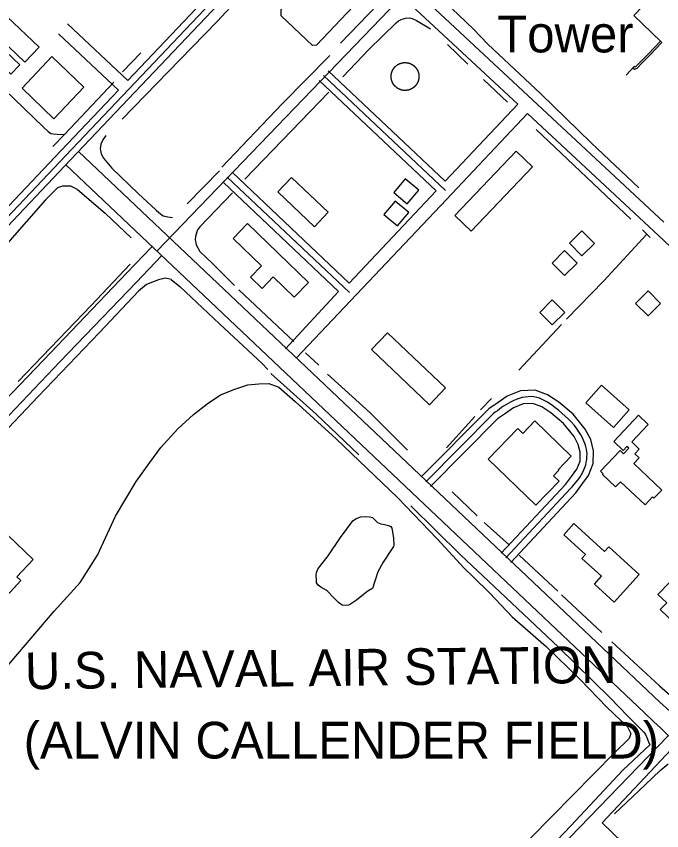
# Model space of a CAD drawing. Extents: x 3683613 to 3738215, y 469626 to 495384.
# Drawn here: x 3696220 to 3697680, y 483982 to 485823 of the extents above; entities that cross this region are included whole.
import ezdxf

# ---------------------------------------------------------------- set-up
doc = ezdxf.new("R2010")
doc.units = 0
for name, color, linetype in [('V-BLDG-IDEN', 7, 'Continuous'), ('V-BLDG-OTLN', 7, 'Continuous'), ('V-DOMW-IDEN', 7, 'Continuous'), ('V-DOMW-TANK', 7, 'Continuous'), ('V-ROAD-CNTR', 7, 'Continuous'), ('V-SITE-OTLN', 7, 'Continuous'), ('V-TOPO-SHOR', 7, 'Continuous'), ('V-UTIL-LINE', 7, 'Continuous')]:
    doc.layers.add(name, color=color, linetype=linetype)

msp = doc.modelspace()

# ---------------------------------------------------------------- linework, layer by layer
at = {"layer": 'V-BLDG-OTLN'}
for points in [[(3696925.1, 485938), (3696996.9, 485871.2), (3696996, 485859.8), (3696899.4, 485757.8), (3696890.2, 485757.5), (3696819.6, 485824.5), (3696819.4, 485838.4), (3696915.4, 485938.3)], [(3696118.3, 485817.2), (3696228.1, 485713.7), (3696207.9, 485692.3), (3696098.7, 485795.2)], [(3696199.1, 485822.8), (3696271.8, 485753.6), (3696239.5, 485719.7), (3696166.1, 485789.6)], [(3696300.7, 485732.5), (3696373.4, 485662.7), (3696305.2, 485591.7), (3696233.5, 485660.5)], [(3697212, 485372.9), (3697350.9, 485517.9), (3697387.9, 485482.5), (3697249.1, 485337.4)], [(3696842.6, 485458.9), (3696925.9, 485380), (3696895.1, 485347.5), (3696811.8, 485426.4)], [(3697100, 485455.6), (3697074.3, 485425), (3697104.9, 485399.3), (3697130.7, 485429.9)], [(3697077.7, 485405.4), (3697052, 485374.8), (3697082.6, 485349.1), (3697108.4, 485379.7)], [(3696743.1, 485354.6), (3696881.3, 485221.3), (3696849.3, 485188.1), (3696801.8, 485233.9), (3696776.9, 485208.1), (3696750.3, 485233.7), (3696774.9, 485259.2), (3696710.7, 485321)], [(3697499.6, 485281.6), (3697528, 485309.8), (3697499.8, 485338.2), (3697471.4, 485309.9)], [(3697460.6, 485237), (3697489, 485265.2), (3697460.7, 485293.5), (3697432.4, 485265.3)], [(3697621.3, 485173.9), (3697649.7, 485145.8), (3697677.9, 485174.1), (3697649.5, 485202.3)], [(3697432.7, 485125.5), (3697461.1, 485153.7), (3697432.9, 485182), (3697404.5, 485153.8)], [(3697155.1, 484945), (3697023.9, 485069.7), (3697060, 485107.7), (3697191.2, 484983)], [(3697571, 484893.8), (3697508.5, 484949.6), (3697544.1, 484989.5), (3697606.6, 484933.7)], [(3697287.8, 484821.6), (3697354.8, 484891.1), (3697366.2, 484880.2), (3697393.1, 484908.2), (3697475.8, 484828.5), (3697446.3, 484797.8), (3697447.4, 484796.8), (3697435.3, 484784.2), (3697448, 484771.9), (3697395.7, 484717.6)], [(3697680.3, 484751.9), (3697662.8, 484733.4), (3697659.6, 484736.4), (3697642.6, 484718.5), (3697587.2, 484770.9), (3697576, 484759), (3697546.4, 484787.1), (3697547.9, 484788.6), (3697541.6, 484794.6), (3697586.2, 484841.6), (3697593.9, 484834.3), (3697605.6, 484846.6), (3697601.4, 484850.5), (3697593.2, 484841.8), (3697571.8, 484862.1), (3697627.6, 484921), (3697649.8, 484899.9), (3697612.6, 484860.7), (3697629.4, 484844.8), (3697619.4, 484834.3), (3697629.3, 484824.9), (3697617, 484812)], [(3696169.4, 484644), (3696154.5, 484628), (3696168.9, 484614.3), (3696201.8, 484649), (3696258.6, 484595.2), (3696221.4, 484556.1), (3696230.8, 484547.2), (3696182.1, 484495.8), (3696046.1, 484624.9), (3696052.2, 484631.3), (3696046.2, 484636.9), (3696108.1, 484702.2)], [(3697629.5, 484560.9), (3697572.9, 484498.7), (3697528, 484539.5), (3697544, 484557.1), (3697499.9, 484597.2), (3697507.9, 484606), (3697458.6, 484650.9), (3697481.8, 484676.4), (3697551.2, 484613.3), (3697560.6, 484623.5)], [(3697895.6, 484510.5), (3697777.2, 484387.8), (3697745.6, 484418.2), (3697741.5, 484414), (3697709.5, 484444.9), (3697712.3, 484447.8), (3697677.1, 484481.7), (3697691.7, 484496.8), (3697671.8, 484516), (3697750.6, 484597.6), (3697778.3, 484571), (3697793, 484586.3), (3697800.6, 484579), (3697803.2, 484581.7), (3697817.2, 484568.3), (3697814.1, 484565), (3697833.4, 484546.4), (3697844.4, 484557.9), (3697852.3, 484550.3), (3697855, 484553.2), (3697863.1, 484545.4), (3697861.3, 484543.5)]]:
    msp.add_lwpolyline(points, close=True, dxfattribs=at)
at = {"layer": 'V-DOMW-TANK'}
for points in [[(3697071.1, 485674), (3697070.9, 485674.5), (3697070.7, 485675), (3697070.5, 485675.5), (3697070.3, 485676), (3697070.1, 485676.5), (3697069.9, 485677.1), (3697069.7, 485677.6), (3697069.6, 485678.1), (3697069.4, 485678.6), (3697069.3, 485679.2), (3697069.1, 485679.7), (3697069, 485680.2), (3697068.9, 485680.8), (3697068.8, 485681.3), (3697068.7, 485681.9), (3697068.6, 485682.4), (3697068.5, 485682.9), (3697068.5, 485683.5), (3697068.4, 485684), (3697068.4, 485684.6), (3697068.3, 485685.1), (3697068.3, 485685.7), (3697068.3, 485686.2), (3697068.3, 485686.8), (3697068.3, 485687.3), (3697068.3, 485687.9), (3697068.3, 485688.4), (3697068.3, 485689), (3697068.4, 485689.5), (3697068.4, 485690.1), (3697068.5, 485690.6), (3697068.5, 485691.2), (3697068.6, 485691.7), (3697068.7, 485692.3), (3697068.8, 485692.8), (3697068.9, 485693.3), (3697069, 485693.9), (3697069.1, 485694.4), (3697069.3, 485694.9), (3697069.4, 485695.5), (3697069.6, 485696), (3697069.7, 485696.5), (3697069.9, 485697), (3697070.1, 485697.6), (3697070.3, 485698.1), (3697070.5, 485698.6), (3697070.7, 485699.1), (3697070.9, 485699.6), (3697071.1, 485700.1), (3697071.3, 485700.6), (3697071.6, 485701.1), (3697071.8, 485701.6), (3697072.1, 485702.1), (3697072.4, 485702.6), (3697072.6, 485703), (3697072.9, 485703.5), (3697073.2, 485704), (3697073.5, 485704.4), (3697073.8, 485704.9), (3697074.1, 485705.3), (3697074.5, 485705.8), (3697074.8, 485706.2), (3697075.1, 485706.7), (3697075.5, 485707.1), (3697075.8, 485707.5), (3697076.2, 485707.9), (3697076.5, 485708.3), (3697076.9, 485708.7), (3697077.3, 485709.1), (3697077.7, 485709.5), (3697078.1, 485709.9), (3697078.5, 485710.3), (3697078.9, 485710.6), (3697079.3, 485711), (3697079.7, 485711.4), (3697080.2, 485711.7), (3697080.6, 485712), (3697081, 485712.4), (3697081.5, 485712.7), (3697081.9, 485713), (3697082.4, 485713.3), (3697082.9, 485713.6), (3697083.3, 485713.9), (3697083.8, 485714.2), (3697084.3, 485714.5), (3697084.7, 485714.7), (3697085.2, 485715), (3697085.7, 485715.2), (3697086.2, 485715.5), (3697086.7, 485715.7), (3697087.2, 485715.9), (3697087.7, 485716.2), (3697088.2, 485716.4), (3697088.7, 485716.6), (3697089.3, 485716.7), (3697089.8, 485716.9), (3697090.3, 485717.1), (3697090.8, 485717.3), (3697091.4, 485717.4), (3697091.9, 485717.5)], [(3697091.9, 485717.5), (3697092.4, 485717.7), (3697093, 485717.8), (3697093.5, 485717.9), (3697094, 485718), (3697094.6, 485718.1), (3697095.1, 485718.2), (3697095.7, 485718.3), (3697096.2, 485718.3), (3697096.8, 485718.4), (3697097.3, 485718.5), (3697097.9, 485718.5), (3697098.4, 485718.5), (3697099, 485718.5), (3697099.5, 485718.5), (3697100.1, 485718.5), (3697100.6, 485718.5), (3697101.2, 485718.5), (3697101.7, 485718.5), (3697102.2, 485718.5), (3697102.8, 485718.4), (3697103.3, 485718.3), (3697103.9, 485718.3), (3697104.4, 485718.2), (3697105, 485718.1), (3697105.5, 485718), (3697106.1, 485717.9), (3697106.6, 485717.8), (3697107.1, 485717.7), (3697107.7, 485717.5), (3697108.2, 485717.4), (3697108.7, 485717.2), (3697109.2, 485717.1), (3697109.8, 485716.9), (3697110.3, 485716.7), (3697110.8, 485716.6), (3697111.3, 485716.4), (3697111.8, 485716.1), (3697112.3, 485715.9), (3697112.8, 485715.7), (3697113.3, 485715.5), (3697113.8, 485715.2), (3697114.3, 485715), (3697114.8, 485714.7), (3697115.3, 485714.5), (3697115.8, 485714.2), (3697116.2, 485713.9), (3697116.7, 485713.6), (3697117.2, 485713.3), (3697117.6, 485713), (3697118.1, 485712.7), (3697118.5, 485712.4), (3697119, 485712), (3697119.4, 485711.7), (3697119.8, 485711.3), (3697120.2, 485711), (3697120.6, 485710.6), (3697121.1, 485710.3), (3697121.5, 485709.9), (3697121.9, 485709.5), (3697122.2, 485709.1), (3697122.6, 485708.7), (3697123, 485708.3), (3697123.4, 485707.9), (3697123.7, 485707.5), (3697124.1, 485707.1), (3697124.4, 485706.7), (3697124.8, 485706.2), (3697125.1, 485705.8), (3697125.4, 485705.3), (3697125.7, 485704.9), (3697126, 485704.4), (3697126.3, 485704), (3697126.6, 485703.5), (3697126.9, 485703), (3697127.2, 485702.6), (3697127.5, 485702.1), (3697127.7, 485701.6), (3697128, 485701.1), (3697128.2, 485700.6), (3697128.4, 485700.1), (3697128.7, 485699.6), (3697128.9, 485699.1), (3697129.1, 485698.6), (3697129.3, 485698.1), (3697129.5, 485697.6), (3697129.6, 485697), (3697129.8, 485696.5), (3697130, 485696), (3697130.1, 485695.5), (3697130.3, 485694.9), (3697130.4, 485694.4), (3697130.5, 485693.9), (3697130.6, 485693.3), (3697130.7, 485692.8), (3697130.8, 485692.2), (3697130.9, 485691.7), (3697131, 485691.2), (3697131.1, 485690.6), (3697131.1, 485690.1), (3697131.2, 485689.5)], [(3697131.2, 485689.5), (3697131.2, 485689), (3697131.2, 485688.4), (3697131.3, 485687.9), (3697131.3, 485687.3), (3697131.3, 485686.8), (3697131.3, 485686.2), (3697131.2, 485685.7), (3697131.2, 485685.1), (3697131.2, 485684.6), (3697131.1, 485684), (3697131.1, 485683.5), (3697131, 485682.9), (3697130.9, 485682.4), (3697130.8, 485681.8), (3697130.7, 485681.3), (3697130.6, 485680.8), (3697130.5, 485680.2), (3697130.4, 485679.7), (3697130.3, 485679.2), (3697130.1, 485678.6), (3697130, 485678.1), (3697129.8, 485677.6), (3697129.6, 485677), (3697129.5, 485676.5), (3697129.3, 485676), (3697129.1, 485675.5), (3697128.9, 485675), (3697128.7, 485674.5), (3697128.4, 485674), (3697128.2, 485673.5), (3697128, 485673), (3697127.7, 485672.5), (3697127.5, 485672), (3697127.2, 485671.5), (3697126.9, 485671.1), (3697126.6, 485670.6), (3697126.3, 485670.1), (3697126, 485669.7), (3697125.7, 485669.2), (3697125.4, 485668.7), (3697125.1, 485668.3), (3697124.8, 485667.9), (3697124.4, 485667.4), (3697124.1, 485667), (3697123.7, 485666.6), (3697123.4, 485666.2), (3697123, 485665.8), (3697122.6, 485665.4), (3697122.2, 485665), (3697121.8, 485664.6), (3697121.4, 485664.2), (3697121, 485663.8), (3697120.6, 485663.5), (3697120.2, 485663.1), (3697119.8, 485662.7), (3697119.4, 485662.4), (3697118.9, 485662.1), (3697118.5, 485661.7), (3697118.1, 485661.4), (3697117.6, 485661.1), (3697117.2, 485660.8), (3697116.7, 485660.5), (3697116.2, 485660.2), (3697115.8, 485659.9), (3697115.3, 485659.6), (3697114.8, 485659.4), (3697114.3, 485659.1), (3697113.8, 485658.9), (3697113.3, 485658.6), (3697112.8, 485658.4), (3697112.3, 485658.2), (3697111.8, 485657.9), (3697111.3, 485657.7), (3697110.8, 485657.5), (3697110.3, 485657.3), (3697109.8, 485657.2), (3697109.2, 485657), (3697108.7, 485656.8), (3697108.2, 485656.7), (3697107.6, 485656.5), (3697107.1, 485656.4), (3697106.6, 485656.3), (3697106, 485656.2), (3697105.5, 485656.1), (3697105, 485656), (3697104.4, 485655.9), (3697103.9, 485655.8), (3697103.3, 485655.7), (3697102.8, 485655.7), (3697102.2, 485655.6), (3697101.7, 485655.6), (3697101.1, 485655.6), (3697100.6, 485655.6), (3697100, 485655.5), (3697099.5, 485655.5), (3697098.9, 485655.6), (3697098.4, 485655.6), (3697097.8, 485655.6), (3697097.3, 485655.6), (3697096.7, 485655.7)], [(3697096.7, 485655.7), (3697096.2, 485655.7), (3697095.7, 485655.8), (3697095.1, 485655.9), (3697094.6, 485656), (3697094, 485656.1), (3697093.5, 485656.2), (3697092.9, 485656.3), (3697092.4, 485656.4), (3697091.9, 485656.5), (3697091.3, 485656.7), (3697090.8, 485656.8), (3697090.3, 485657), (3697089.8, 485657.2), (3697089.2, 485657.4), (3697088.7, 485657.5), (3697088.2, 485657.7), (3697087.7, 485657.9), (3697087.2, 485658.2), (3697086.7, 485658.4), (3697086.2, 485658.6), (3697085.7, 485658.9), (3697085.2, 485659.1), (3697084.7, 485659.4), (3697084.3, 485659.6), (3697083.8, 485659.9), (3697083.3, 485660.2), (3697082.8, 485660.5), (3697082.4, 485660.8), (3697081.9, 485661.1), (3697081.5, 485661.4), (3697081, 485661.7), (3697080.6, 485662.1), (3697080.2, 485662.4), (3697079.7, 485662.7), (3697079.3, 485663.1), (3697078.9, 485663.5), (3697078.5, 485663.8), (3697078.1, 485664.2), (3697077.7, 485664.6), (3697077.3, 485665), (3697076.9, 485665.4), (3697076.5, 485665.8), (3697076.2, 485666.2), (3697075.8, 485666.6), (3697075.5, 485667), (3697075.1, 485667.4), (3697074.8, 485667.9), (3697074.4, 485668.3), (3697074.1, 485668.8), (3697073.8, 485669.2), (3697073.5, 485669.7), (3697073.2, 485670.1), (3697072.9, 485670.6), (3697072.6, 485671.1), (3697072.3, 485671.5), (3697072.1, 485672), (3697071.8, 485672.5), (3697071.6, 485673), (3697071.3, 485673.5), (3697071.1, 485674)]]:
    msp.add_lwpolyline(points, dxfattribs=at)
at = {"layer": 'V-ROAD-CNTR'}
for points in [[(3694989.5, 484100.6), (3695664, 484803.4), (3696332.2, 485508.7), (3697143.5, 486363.2), (3697961.7, 487220.9)], [(3696538.3, 485292.1), (3697103.2, 485879.3), (3697647.9, 486465.6), (3698110.4, 486944.2), (3698227.4, 487193.3)], [(3696472.5, 485678.3), (3697132.7, 486373.5), (3697406.4, 486660.4)], [(3695808.7, 484934.3), (3696343.1, 485498.4), (3696881.4, 486065.4)], [(3697113.4, 485890.3), (3697684.8, 485357.8)], [(3697092.8, 485868.5), (3697355, 485624.2)], [(3696336.2, 485805.8), (3696472.5, 485678.3)], [(3696315.7, 485783.9), (3696451.8, 485656.5)], [(3696925.9, 485699.9), (3697190.7, 485450.3)], [(3696905.3, 485678.1), (3697170.1, 485428.5)], [(3696915.6, 485689), (3697191.5, 485429)], [(3695090.7, 484227.7), (3695653.2, 484813.7), (3696321.3, 485519.1), (3696451.8, 485656.5)], [(3697190.7, 485450.3), (3697355, 485624.2)], [(3696854.4, 485050.7), (3697193.2, 485409.3), (3697376.9, 485603.7)], [(3697376.9, 485603.7), (3697684.2, 485317.4), (3698245.6, 484780.3)], [(3697676, 484272.7), (3696361.2, 485517.6)], [(3697640.4, 484249.3), (3696332.3, 485487)], [(3696697.7, 485459.8), (3696973.8, 485198.7)], [(3696709.1, 485469.7), (3696973.1, 485220.1), (3697170.1, 485428.5)], [(3696688.5, 485447.9), (3696949, 485200.6), (3696829.6, 485071.1)], [(3696470.4, 485242.9), (3696527.1, 485302.1)], [(3696492.1, 485222.2), (3696548.8, 485281.4)], [(3696297.5, 485062.4), (3696470.4, 485242.9)], [(3696319.2, 485041.6), (3696492.1, 485222.2)], [(3696124.6, 484881.8), (3696297.5, 485062.4)], [(3696146.3, 484861.1), (3696319.2, 485041.6)], [(3697338.9, 484588.6), (3697485.7, 484745.5), (3697500, 484764.8), (3697515, 484785), (3697525.5, 484811.8), (3697526, 484840.8), (3697519.7, 484866.1), (3697507.1, 484890), (3697479.7, 484923.3), (3697447.6, 484950.8), (3697422.3, 484967.5), (3697393.8, 484977.8), (3697360.8, 484976.6), (3697330.9, 484964.1), (3697310.2, 484950), (3697289.6, 484936), (3697135.9, 484781.6)], [(3697317, 484609), (3697462.6, 484764.8), (3697475.9, 484782.7), (3697488.5, 484799.6), (3697495.6, 484817.7), (3697496, 484837.4), (3697491.5, 484855.3), (3697482, 484873.3), (3697458.2, 484902.2), (3697429.5, 484926.8), (3697408.8, 484940.4), (3697389.1, 484947.6), (3697367.3, 484946.8), (3697345.3, 484937.6), (3697327.1, 484925.2), (3697308.9, 484912.8), (3697157.1, 484760.4)], [(3697299.3, 484924.4), (3697146.5, 484771)], [(3697328, 484598.8), (3697474.2, 484755.2)], [(3696977.4, 483379.4), (3696892, 483294.1), (3696669.8, 483059.1), (3696649.4, 483042.1), (3696617.9, 483064.7), (3697149.5, 483632.8), (3697161.9, 483645.4), (3697693.9, 484195.8)], [(3697763.1, 483856.1), (3697728.7, 483822.7), (3697545.3, 484000), (3697714.9, 484179.2)]]:
    msp.add_lwpolyline(points, dxfattribs=at)
for points in [[(3697474.2, 484755.2), (3697501.8, 484792.3), (3697511, 484839.1), (3697494.5, 484881.7), (3697438.6, 484938.8), (3697391.4, 484962.7), (3697338.1, 484950.9), (3697299.3, 484924.4)], [(3698104.2, 484033.2), (3698004.6, 484055.2), (3697867.9, 484110.6), (3697776.7, 484180.6), (3697738.5, 484215.2), (3697676, 484272.7)], [(3698086.4, 483992.1), (3697951.8, 484023.2), (3697828.2, 484088.5), (3697699.5, 484193.6), (3697640.4, 484249.3)]]:
    msp.add_spline(points, degree=3, dxfattribs=at)
at = {"layer": 'V-SITE-OTLN'}
msp.add_lwpolyline([(3696189.1, 484340.9), (3696306.3, 484478), (3696365.1, 484542.8), (3696403.8, 484604.7), (3696444.9, 484692.8), (3696491.4, 484771.6), (3696522.8, 484814.3), (3696547.7, 484848.4), (3696585.9, 484890.3), (3696621, 484922.5), (3696652.5, 484946.9), (3696682.1, 484967.3), (3696715.1, 484980.2), (3696744.5, 484990.3), (3696769.1, 484992.5), (3696791.4, 484993.1), (3696814.6, 484984.5), (3696850.9, 484952.2), (3696944.3, 484868.1), (3697083.8, 484734.8), (3697172.3, 484641.7), (3697233.5, 484575.6), (3697253.6, 484555.6), (3697291.5, 484519.2), (3697342.2, 484465.4), (3697418.8, 484398.3), (3697495.2, 484324.3), (3697555.9, 484261.1), (3697602.8, 484217), (3697610.4, 484202), (3697606.7, 484190.6), (3697573.9, 484157.7), (3697383.2, 483964.8)], dxfattribs=at)
at = {"layer": 'V-TOPO-SHOR'}
for p, q in [((3696733.2, 485874.8), (3696675, 485811.7)), ((3696675, 485811.7), (3696590.6, 485724.5)), ((3697195.5, 485759.5), (3697241.6, 485714.9)), ((3696502.2, 485740.3), (3696460.8, 485697.5)), ((3697017.8, 485748), (3696959.4, 485686.4)), ((3696590.6, 485724.5), (3696460, 485590.9)), ((3697277.4, 485680.5), (3697331.5, 485629.2)), ((3696927, 485651.3), (3696737.6, 485454.9)), ((3697396.3, 485567.4), (3697610.3, 485364.5)), ((3696679.9, 485474), (3696607.1, 485399.1)), ((3696723.6, 485204.7), (3696848, 485087.7)), ((3697357.1, 485023.2), (3697453.5, 485126.3)), ((3696874.5, 485062.6), (3696904.8, 485034.4)), ((3697270.8, 484933.3), (3697295.6, 484958.7)), ((3697193.2, 484847.8), (3697257.4, 484918.7)), ((3697206.1, 484747.9), (3697262.6, 484693.7)), ((3697278.6, 484678.9), (3697336, 484627.3)), ((3697358, 484604.5), (3697445.7, 484523.3)), ((3697454, 484515), (3697545, 484430.1))]:
    msp.add_line(p, q, dxfattribs=at)
for points in [[(3696918.2, 486018.1), (3697021.9, 485922), (3697045.9, 485895.5), (3697050.8, 485889.5), (3697052.7, 485884.8), (3697052.9, 485879.2), (3697051.2, 485870.1), (3697038, 485850.2), (3696953.6, 485762.1)], [(3697628.6, 485435.5), (3697520.8, 485537.3), (3697406.8, 485647.8), (3697286.9, 485760), (3697254.6, 485794.2), (3697220.4, 485826.7), (3697192.2, 485853.3), (3697181.5, 485864.4), (3697175.4, 485872.7), (3697171.7, 485878.7), (3697169.2, 485884.9), (3697167.5, 485891.4), (3697168.2, 485897.7), (3697172.7, 485906.5), (3697190.8, 485925.7)], [(3696073, 485831.3), (3696075.8, 485800), (3696079.2, 485783.4), (3696084.4, 485769.7), (3696090.6, 485759.6), (3696100.4, 485748.7), (3696113.9, 485734.8), (3696135.4, 485712.8), (3696150.4, 485698.3), (3696281.2, 485573.6), (3696292.7, 485562.7), (3696298.8, 485558.4), (3696303.8, 485557.4), (3696312.6, 485556.6), (3696329.6, 485555.7)], [(3697017.8, 485748), (3697079.9, 485808.7), (3697085.3, 485812.9), (3697091.3, 485815.7), (3697101, 485818.8), (3697110.3, 485819.4), (3697115.5, 485817.9), (3697125.9, 485813.7), (3697157.5, 485794.5)], [(3696929.4, 485734.8), (3696821.8, 485625), (3696685.6, 485481.8)], [(3696441.1, 485674.5), (3696329.6, 485555.7), (3696303.3, 485528.6)], [(3696423.3, 485553.3), (3696416, 485543.7), (3696411.7, 485534.1), (3696409.9, 485523.9), (3696412.3, 485512.3), (3696417.6, 485502.8), (3696436.2, 485479.7), (3696495.9, 485422.8), (3696536.8, 485385), (3696543.1, 485379.3), (3696552.6, 485372.3), (3696562.9, 485370), (3696573.6, 485368.2)], [(3696359, 485431.9), (3696343.9, 485439.3), (3696325.1, 485438.9), (3696313.5, 485435.4), (3696286.4, 485408.4), (3696200.4, 485310.4), (3696050.5, 485153.5)], [(3696359, 485431.9), (3696421.4, 485378.3), (3696480.1, 485322)], [(3696709.8, 485424.2), (3696635.8, 485347.3), (3696630.3, 485340.3), (3696628.5, 485335.7), (3696625.6, 485325.5), (3696625.1, 485318.4), (3696627.4, 485306.3), (3696635.6, 485291.4), (3696664.3, 485264.2), (3696714.2, 485214.3)], [(3697464.8, 485138.5), (3697549.2, 485224.8), (3697646.9, 485330.3)], [(3697636.5, 485340.1), (3697646.9, 485330.3), (3697654.5, 485323.2)], [(3696478, 485262.7), (3696389.5, 485169.6), (3696224.4, 484997.7)], [(3696570.9, 485228.3), (3696558, 485231), (3696541.8, 485227.5), (3696515, 485217), (3696496.9, 485201.6), (3696408.9, 485108.4), (3696269.5, 484963.2), (3696108.8, 484794)], [(3696570.9, 485228.3), (3696590.5, 485211.9), (3696680, 485127.8), (3696776.3, 485037.9), (3696789.1, 485024.8)], [(3696796.5, 485015.2), (3696898.8, 484923.3), (3696995.1, 484831.9)], [(3696924.4, 485014), (3697020.3, 484927.2), (3697105.4, 484842.6)], [(3697112.5, 484716.3), (3697226.3, 484605.2), (3697301.3, 484534), (3697447.2, 484396.8), (3697563.4, 484282.2), (3697602.6, 484241.5), (3697635.7, 484209.3), (3697639.9, 484205), (3697643.5, 484199.2), (3697646.9, 484192.7), (3697650.3, 484183.1), (3697653.5, 484176)], [(3696921.5, 484526), (3696909.3, 484532.7), (3696903.2, 484537), (3696899.8, 484542.4), (3696899.1, 484548.6), (3696898.5, 484559.8), (3696899.5, 484565.9), (3696902.4, 484573.2), (3696907.2, 484579), (3696925.8, 484603.2), (3696953.9, 484644.8), (3696981.9, 484682.1), (3696989.4, 484687.5), (3696999.5, 484691.3), (3697009.8, 484692.3), (3697019.5, 484691.4), (3697026.2, 484689.8), (3697032.2, 484684.3), (3697037.7, 484678.9), (3697044.9, 484675.5), (3697053.4, 484674.4), (3697062.5, 484672.1), (3697067.7, 484669.9), (3697070, 484665.7), (3697073.3, 484643.9), (3697074.3, 484627.1), (3697073.4, 484624.2), (3697070.9, 484619.8), (3697050.4, 484589.2), (3697038.1, 484567.1), (3697032.7, 484550.8), (3697029.1, 484539.1), (3697026.9, 484531.2), (3697024.8, 484528.4), (3697015.2, 484523.3), (3697002, 484513), (3696990, 484503.3), (3696976.5, 484494.3), (3696972.1, 484492), (3696965.9, 484490.7), (3696957.4, 484491.8), (3696949.6, 484497.6), (3696939, 484508.5), (3696923.5, 484524.4), (3696921.5, 484526)], [(3697567.6, 484408.6), (3697675.1, 484309.5), (3697705.2, 484283.2), (3697717.8, 484277.1), (3697727.1, 484273.7), (3697739.9, 484269.5)], [(3697183.8, 483692.3), (3697247.5, 483761.2), (3697370.1, 483883.2), (3697474.9, 483993), (3697592.3, 484118.4), (3697653.5, 484176)], [(3697573.7, 484020.1), (3697642.8, 484085.6), (3697676.9, 484117.9), (3697695.3, 484133.3)]]:
    msp.add_lwpolyline(points, dxfattribs=at)
at = {"layer": 'V-UTIL-LINE'}
for points in [[(3697686.5, 486028.7), (3697690.1, 486034.5), (3697718.4, 486064.5), (3697733.5, 486078.7), (3697777.8, 486125.7), (3697780.6, 486123), (3697812.5, 486155.6), (3697829.5, 486138.5), (3697833.4, 486142.7), (3697878.7, 486099.1), (3697752.7, 485966.4), (3697617.1, 485825.1), (3697677.3, 485766.9), (3697650.3, 485738.6), (3697633.5, 485721.6), (3697620.3, 485708.1), (3697618.3, 485709.8), (3697600.1, 485690.3)], [(3697615.2, 485706.5), (3697618.7, 485703.8), (3697624.6, 485705.6), (3697636.3, 485717.6), (3697654.3, 485735.7), (3697680.4, 485764.1), (3697677.3, 485766.9)]]:
    msp.add_lwpolyline(points, dxfattribs=at)

# ---------------------------------------------------------------- texts
at = {"layer": 'V-BLDG-IDEN'}
msp.add_text('U.S. NAVAL AIR STATION', height=83, rotation=0.6237, dxfattribs=at).set_placement((3696240.2, 484301.6))
msp.add_text('(ALVIN CALLENDER FIELD)', height=83, dxfattribs=at).set_placement((3696237.1, 484145.1))
at = {"layer": 'V-DOMW-IDEN'}
msp.add_text('Tower', height=83, dxfattribs=at).set_placement((3697308.3, 485741.5))

doc.saveas('drawing.dxf')
